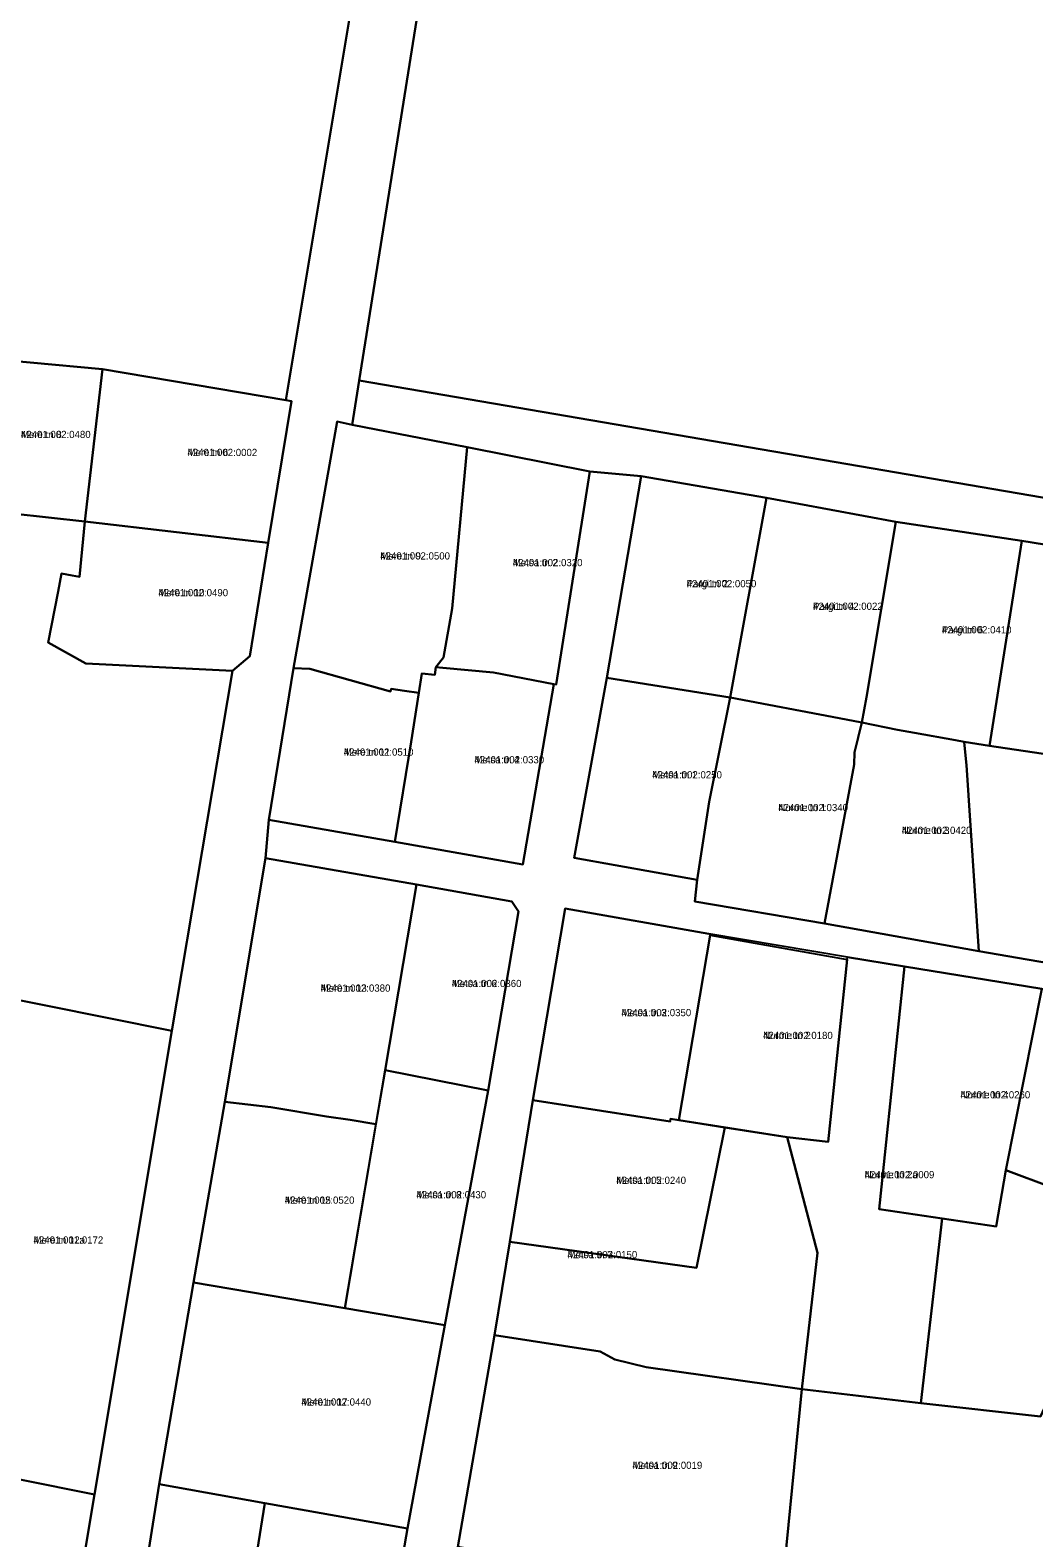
# Model space of a CAD drawing. Extents: x 595979 to 597983, y 6604231 to 6607350.
# Drawn here: x 596596.1 to 596804.9, y 6605736 to 6606049.7 of the extents above; entities that cross this region are included whole.
import ezdxf

# ---------------------------------------------------------------- set-up
doc = ezdxf.new("R2010")
doc.units = 0
for name, color, linetype in [('L_AADRESS', 7, 'Continuous'), ('PIIR', 7, 'Continuous'), ('TUNNUS', 7, 'Continuous')]:
    doc.layers.add(name, color=color, linetype=linetype)

msp = doc.modelspace()

# ---------------------------------------------------------------- linework, layer by layer
at = {"layer": 'PIIR'}
for points in [[(596695.91, 6606173.63), (596664.52, 6605976.79), (596663.07, 6605967.51), (596659.94, 6605968.22), (596650.85, 6605916.95), (596645.72, 6605885.35), (596645.06, 6605877.39), (596636.6, 6605826.7), (596630.08, 6605789.08), (596622.92, 6605747.16), (596616.69, 6605707.7), (596610.34, 6605668.35), (596602.72, 6605622.28), (596599.67, 6605601.99), (596540.44, 6605248.17)], [(597083.05, 6606050.71), (597087.59, 6606045.02), (597057.4, 6606015.57), (597045.35, 6606028.13), (597042.19, 6606029.76), (597014.23, 6606031.96), (596997.32, 6606005.56), (596975.98, 6605972.14), (596955.37, 6605940.6), (596956.04, 6605934.38), (596951.35, 6605927.69), (596664.52, 6605976.79), (596695.91, 6606173.63)], [(596676, 6606132.91), (596649.26, 6605972.7), (596611.15, 6605979.13), (596580.95, 6605981.91)], [(596586.03, 6605605.02), (596609.5, 6605744.98), (596625.57, 6605841.47), (596638.15, 6605916.36), (596641.76, 6605919.43), (596645.62, 6605942.97), (596650.45, 6605972.44), (596649.26, 6605972.7), (596676, 6606132.91)], [(596828.54, 6605939.21), (596802.41, 6605943.38), (596776.17, 6605947.33), (596749.3, 6605952.37), (596723.21, 6605956.89), (596712.54, 6605957.85), (596687.01, 6605962.89), (596663.07, 6605967.51), (596664.52, 6605976.79), (596951.35, 6605927.69)], [(596667.81, 6605698.76), (596674.62, 6605737.93), (596682.38, 6605780.23), (596691.38, 6605829.02), (596697.66, 6605866.27), (596696.27, 6605868.36), (596676.46, 6605871.91), (596645.06, 6605877.39), (596645.72, 6605885.35), (596671.97, 6605880.77), (596698.62, 6605876.1), (596705.06, 6605913.62), (596705.52, 6605913.55), (596712.54, 6605957.85), (596723.21, 6605956.89), (596716.04, 6605914.9), (596709.27, 6605877.49), (596734.86, 6605872.91), (596734.34, 6605868.4), (596761.37, 6605863.79), (596793.49, 6605858.05), (596814.02, 6605854.49)], [(596577.17, 6605950.76), (596607.48, 6605947.4), (596606.32, 6605935.93), (596604.83, 6605936.19), (596602.63, 6605936.58), (596601.91, 6605932.9), (596599.82, 6605922.26), (596607.67, 6605917.91), (596638.15, 6605916.36), (596625.57, 6605841.47), (596585.81, 6605849.41)], [(596880.63, 6605726.43), (596886.61, 6605739.74), (596893.02, 6605755.31), (596898.3, 6605767.83), (596908.48, 6605792.56), (596907.11, 6605797.35), (596882.35, 6605813.02), (596875.13, 6605813.17), (596868.3, 6605807.18), (596863.71, 6605798.49), (596859.1, 6605800.95), (596855.44, 6605821.22), (596860.57, 6605827.16), (596836.88, 6605844.3), (596806.56, 6605850.22), (596777.97, 6605854.86), (596766.12, 6605856.78), (596737.27, 6605861.65), (596707.41, 6605866.94), (596700.7, 6605827.04), (596695.89, 6605797.54), (596692.66, 6605778.16), (596685.03, 6605734.09)], [(596517.58, 6605763.43), (596609.5, 6605744.98), (596586.03, 6605605.02)]]:
    msp.add_lwpolyline(points, dxfattribs=at)
for points in [[(596580.95, 6605981.91), (596611.15, 6605979.13), (596607.48, 6605947.4), (596577.17, 6605950.76)], [(596611.15, 6605979.13), (596649.26, 6605972.7), (596650.45, 6605972.44), (596645.62, 6605942.97), (596607.48, 6605947.4)], [(596659.94, 6605968.22), (596663.07, 6605967.51), (596687.01, 6605962.89), (596683.89, 6605929.35), (596682.11, 6605919.16), (596680.46, 6605917.15), (596680.31, 6605915.55), (596677.56, 6605915.81), (596676.94, 6605911.78), (596673.95, 6605912.2), (596671.2, 6605912.6), (596671.05, 6605912.07), (596654.26, 6605916.8), (596650.85, 6605916.95)], [(596687.01, 6605962.89), (596712.54, 6605957.85), (596705.52, 6605913.55), (596705.06, 6605913.62), (596692.49, 6605915.99), (596681.95, 6605917.01), (596680.46, 6605917.15), (596682.11, 6605919.16), (596683.89, 6605929.35)], [(596716.04, 6605914.9), (596723.21, 6605956.89), (596749.3, 6605952.37), (596741.74, 6605910.79)], [(596749.3, 6605952.37), (596776.17, 6605947.33), (596770.12, 6605910.85), (596769.14, 6605905.63), (596764.4, 6605906.52), (596741.74, 6605910.79)], [(596604.83, 6605936.19), (596606.32, 6605935.93), (596607.48, 6605947.4), (596645.62, 6605942.97), (596641.76, 6605919.43), (596638.15, 6605916.36), (596607.67, 6605917.91), (596599.82, 6605922.26), (596601.91, 6605932.9), (596602.63, 6605936.58)], [(596776.53, 6605904.1), (596769.14, 6605905.63), (596770.12, 6605910.85), (596776.17, 6605947.33), (596802.41, 6605943.38), (596795.71, 6605900.79), (596790.43, 6605901.62), (596788.6, 6605901.91), (596780.05, 6605903.44)], [(596802.41, 6605943.38), (596828.54, 6605939.21), (596821.66, 6605896.78), (596820.96, 6605897.03), (596795.71, 6605900.79)], [(596650.85, 6605916.95), (596654.26, 6605916.8), (596671.05, 6605912.07), (596671.2, 6605912.6), (596673.95, 6605912.2), (596676.94, 6605911.78), (596675.37, 6605901.59), (596671.97, 6605880.77), (596645.72, 6605885.35)], [(596698.62, 6605876.1), (596671.97, 6605880.77), (596675.37, 6605901.59), (596676.94, 6605911.78), (596677.56, 6605915.81), (596680.31, 6605915.55), (596680.46, 6605917.15), (596681.95, 6605917.01), (596692.49, 6605915.99), (596705.06, 6605913.62)], [(596709.27, 6605877.49), (596716.04, 6605914.9), (596741.74, 6605910.79), (596737.33, 6605889.14), (596734.86, 6605872.91)], [(596741.74, 6605910.79), (596764.4, 6605906.52), (596769.14, 6605905.63), (596767.57, 6605899.37), (596767.54, 6605896.9), (596761.37, 6605863.79), (596734.34, 6605868.4), (596734.86, 6605872.91), (596737.33, 6605889.14)], [(596769.14, 6605905.63), (596776.53, 6605904.1), (596780.05, 6605903.44), (596788.6, 6605901.91), (596790.43, 6605901.62), (596790.77, 6605898.05), (596790.9, 6605896.71), (596793.49, 6605858.05), (596761.37, 6605863.79), (596767.54, 6605896.9), (596767.57, 6605899.37)], [(596790.43, 6605901.62), (596795.71, 6605900.79), (596820.96, 6605897.03), (596814.02, 6605854.49), (596793.49, 6605858.05), (596790.9, 6605896.71), (596790.77, 6605898.05)], [(596645.06, 6605877.39), (596676.46, 6605871.91), (596669.94, 6605833.31), (596668.02, 6605822.05), (596662.64, 6605822.97), (596657.76, 6605823.61), (596646.15, 6605825.62), (596636.6, 6605826.7)], [(596669.94, 6605833.31), (596676.46, 6605871.91), (596696.27, 6605868.36), (596697.66, 6605866.27), (596691.38, 6605829.02)], [(596707.41, 6605866.94), (596737.27, 6605861.65), (596737.53, 6605861.36), (596731.06, 6605822.91), (596729.34, 6605823.18), (596729.24, 6605822.57), (596700.7, 6605827.04)], [(596737.53, 6605861.36), (596766.07, 6605856.29), (596762.15, 6605818.4), (596753.57, 6605819.33), (596731.06, 6605822.91)], [(596766.12, 6605856.78), (596777.97, 6605854.86), (596772.76, 6605804.36), (596785.86, 6605802.44), (596781.4, 6605764.04), (596756.61, 6605766.92), (596759.93, 6605795.3), (596753.57, 6605819.33), (596762.15, 6605818.4), (596766.07, 6605856.29)], [(596777.97, 6605854.86), (596806.56, 6605850.22), (596799.08, 6605812.46), (596797.08, 6605800.79), (596785.86, 6605802.44), (596772.76, 6605804.36)], [(596574.07, 6605790.56), (596585.81, 6605849.41), (596625.57, 6605841.47), (596609.5, 6605744.98), (596517.58, 6605763.43), (596525.06, 6605800.45)], [(596806.56, 6605850.22), (596836.88, 6605844.3), (596808.71, 6605808.89), (596799.08, 6605812.46)], [(596836.88, 6605844.3), (596860.57, 6605827.16), (596855.44, 6605821.22), (596847.24, 6605815.99), (596828.1, 6605801.37), (596821.32, 6605793.9), (596806.3, 6605761.22), (596781.4, 6605764.04), (596785.86, 6605802.44), (596797.08, 6605800.79), (596799.08, 6605812.46), (596808.71, 6605808.89)], [(596691.38, 6605829.02), (596682.38, 6605780.23), (596661.52, 6605783.78), (596669.94, 6605833.31)], [(596636.6, 6605826.7), (596646.15, 6605825.62), (596657.76, 6605823.61), (596662.64, 6605822.97), (596668.02, 6605822.05), (596661.52, 6605783.78), (596630.08, 6605789.08)], [(596695.89, 6605797.54), (596700.7, 6605827.04), (596729.24, 6605822.57), (596729.34, 6605823.18), (596740.61, 6605821.39), (596734.71, 6605792.19)], [(596695.89, 6605797.54), (596734.71, 6605792.19), (596740.61, 6605821.39), (596753.57, 6605819.33), (596759.93, 6605795.3), (596756.61, 6605766.92), (596724.22, 6605771.51), (596717.73, 6605773.06), (596714.7, 6605774.77), (596692.66, 6605778.16)], [(596783.16, 6605636.35), (596742.46, 6605643.65), (596743.26, 6605663.24), (596743.76, 6605681.63), (596750.48, 6605716.38), (596683.77, 6605728.06), (596685.03, 6605734.09), (596751.3, 6605722.5), (596753.04, 6605730.24), (596756.61, 6605766.92), (596781.4, 6605764.04), (596806.3, 6605761.22), (596821.32, 6605793.9), (596835.19, 6605774.82), (596828.35, 6605763.51), (596814.68, 6605734.88), (596800.26, 6605709.74), (596788.69, 6605683.33), (596797.85, 6605679.12), (596789.61, 6605661.31), (596786.57, 6605654.73), (596789.87, 6605651.91)], [(596630.08, 6605789.08), (596661.52, 6605783.78), (596682.38, 6605780.23), (596674.62, 6605737.93), (596644.93, 6605743.23), (596622.92, 6605747.16)], [(596692.66, 6605778.16), (596714.7, 6605774.77), (596717.73, 6605773.06), (596724.22, 6605771.51), (596756.61, 6605766.92), (596753.04, 6605730.24), (596751.3, 6605722.5), (596685.03, 6605734.09)], [(596622.92, 6605747.16), (596644.93, 6605743.23), (596638.51, 6605703.28), (596616.69, 6605707.7)], [(596674.62, 6605737.93), (596667.81, 6605698.76), (596638.51, 6605703.28), (596644.93, 6605743.23)]]:
    msp.add_lwpolyline(points, close=True, dxfattribs=at)

# ---------------------------------------------------------------- texts
at = {"layer": 'L_AADRESS'}
for s, p in [('Mere tn 8', (596594.16, 6605964.79)), ('Mere tn 6', (596628.82, 6605961.05)), ('Mere tn 9', (596668.93, 6605939.52)), ('Metsa tn 2', (596696.5, 6605938.13)), ('Pargi tn 2', (596732.67, 6605933.75)), ('Mere tn 10', (596622.76, 6605931.88)), ('Pargi tn 4', (596758.96, 6605929.05)), ('Pargi tn 6', (596785.77, 6605924.15)), ('Mere tn 11', (596661.33, 6605898.72)), ('Metsa tn 4', (596688.52, 6605897.12)), ('Metsa tn 1', (596725.51, 6605893.99)), ('Nurme tn 1', (596751.74, 6605887.17)), ('Nurme tn 3', (596777.43, 6605882.43)), ('Mere tn 13', (596656.53, 6605849.61)), ('Metsa tn 6', (596683.8, 6605850.57)), ('Metsa tn 3', (596719.12, 6605844.51)), ('Nurme tn 2', (596748.57, 6605839.76)), ('Nurme tn 4', (596789.66, 6605827.42)), ('Nurme tn 2a', (596769.71, 6605810.8)), ('Metsa tn 5', (596718.04, 6605809.62)), ('Mere tn 15', (596649.05, 6605805.5)), ('Metsa tn 8', (596676.45, 6605806.62)), ('Mere tn 12a', (596596.79, 6605797.2)), ('Metsa tn 7', (596707.89, 6605794.16)), ('Mere tn 17', (596652.51, 6605763.5)), ('Metsa tn 9', (596721.42, 6605750.33))]:
    msp.add_text(s, height=1.5, dxfattribs=at).set_placement(p)
at = {"layer": 'TUNNUS'}
for s, p in [('42401:002:0480', (596594.16, 6605964.79)), ('42401:002:0002', (596628.82, 6605961.05)), ('42401:002:0500', (596668.93, 6605939.52)), ('42401:002:0320', (596696.5, 6605938.13)), ('42401:002:0050', (596732.67, 6605933.75)), ('42401:002:0490', (596622.76, 6605931.88)), ('42401:002:0022', (596758.96, 6605929.05)), ('42401:002:0410', (596785.77, 6605924.15)), ('42401:002:0510', (596661.33, 6605898.72)), ('42401:002:0330', (596688.52, 6605897.12)), ('42401:002:0250', (596725.51, 6605893.99)), ('42401:002:0340', (596751.74, 6605887.17)), ('42401:002:0420', (596777.43, 6605882.43)), ('42401:002:0380', (596656.53, 6605849.61)), ('42401:002:0360', (596683.8, 6605850.57)), ('42401:002:0350', (596719.12, 6605844.51)), ('42401:002:0180', (596748.57, 6605839.76)), ('42401:002:0260', (596789.66, 6605827.42)), ('42401:002:0009', (596769.71, 6605810.8)), ('42401:002:0240', (596718.04, 6605809.62)), ('42401:002:0520', (596649.05, 6605805.5)), ('42401:002:0430', (596676.45, 6605806.62)), ('42401:001:0172', (596596.79, 6605797.2)), ('42401:002:0150', (596707.89, 6605794.16)), ('42401:002:0440', (596652.51, 6605763.5)), ('42401:002:0019', (596721.42, 6605750.33))]:
    msp.add_text(s, height=1.5, dxfattribs=at).set_placement(p)

doc.saveas('drawing.dxf')
